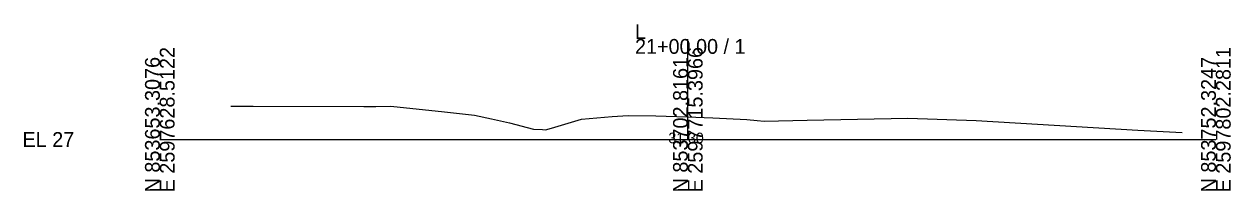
# Model space of a CAD drawing. Extents: x -26 to 1203, y -10 to 9526.
# Drawn here: x 974.3 to 1202.8, y 990.3 to 1021.8 of the extents above; entities that cross this region are included whole.
import ezdxf

# ---------------------------------------------------------------- set-up
doc = ezdxf.new("R2010")
doc.units = 0
for name, color, linetype in [('Exist Cross Section Cell', 7, 'Continuous'), ('Exist XS Center Line Elevation Label', 7, 'Continuous'), ('Exist XS Ground Line', 7, 'Continuous')]:
    doc.layers.add(name, color=color, linetype=linetype)

msp = doc.modelspace()

# ---------------------------------------------------------------- linework, layer by layer
at = {"layer": 'Exist Cross Section Cell'}
for p, q in [((1100, 1000), (1100, 1018.99)), ((1000, 1000), (1100, 1000)), ((1100, 1000), (1200, 1000))]:
    msp.add_line(p, q, dxfattribs=at)
at = {"layer": 'Exist XS Ground Line'}
for p, q in [((1013.46, 1006.33), (1017.7, 1006.29)), ((1017.7, 1006.29), (1038.62, 1006.23)), ((1038.62, 1006.23), (1040.89, 1006.25)), ((1040.89, 1006.25), (1043.76, 1006.29)), ((1043.76, 1006.29), (1053.92, 1005.22)), ((1053.92, 1005.22), (1059.59, 1004.62)), ((1059.59, 1004.62), (1062.82, 1003.88)), ((1062.82, 1003.88), (1066.2, 1003.12)), ((1074.16, 1002.14), (1079.89, 1003.83)), ((1079.89, 1003.83), (1085.67, 1004.33)), ((1085.67, 1004.33), (1088.69, 1004.55)), ((1088.69, 1004.55), (1093.92, 1004.45)), ((1093.92, 1004.45), (1099.86, 1004.3)), ((1099.86, 1004.3), (1104.76, 1004.07)), ((1104.76, 1004.07), (1111.19, 1003.75)), ((1111.19, 1003.75), (1113.15, 1003.58)), ((1113.15, 1003.58), (1114.47, 1003.49)), ((1114.47, 1003.49), (1122.59, 1003.63)), ((1122.59, 1003.63), (1141.66, 1004.02)), ((1141.66, 1004.02), (1154.61, 1003.58)), ((1154.61, 1003.58), (1185.24, 1001.74)), ((1066.2, 1003.12), (1070.78, 1001.98)), ((1070.78, 1001.98), (1072.48, 1001.9)), ((1072.48, 1001.9), (1073.02, 1001.86)), ((1073.02, 1001.86), (1074.16, 1002.14)), ((1185.24, 1001.74), (1193.59, 1001.35))]:
    msp.add_line(p, q, dxfattribs=at)

# ---------------------------------------------------------------- texts
at = {"layer": 'Exist Cross Section Cell'}
for s, p in [('L', (1090, 1018.99)), ('21+00.00 / 1', (1090, 1016.19)), ('EL 27', (974, 998.6))]:
    msp.add_text(s, height=2.8, dxfattribs=at).set_placement(p)
for s, p in [('E 2597628.5122', (1002.8, 990)), ('E 2597715.3966', (1102.8, 990)), ('E 2597802.2811', (1202.8, 990)), ('N 853653.3076', (1000, 990)), ('N 853702.8161', (1100, 990)), ('N 853752.3247', (1200, 990))]:
    msp.add_text(s, height=2.8, rotation=90, dxfattribs=at).set_placement(p)
at = {"layer": 'Exist XS Center Line Elevation Label'}
msp.add_text('31.30', height=2, dxfattribs=at).set_placement((1096.32, 999.3))

doc.saveas('drawing.dxf')
